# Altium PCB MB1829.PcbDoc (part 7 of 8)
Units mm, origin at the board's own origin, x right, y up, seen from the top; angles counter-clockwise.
Board outline 90 x 110 mm, 6 copper layers (Top Layer, Signal Layer 1, Signal Layer 2, Signal Layer 3, Signal Layer 4, Bottom Layer), stack 1.578 mm thick; 466 components, 354 nets, 2058 pads, 1522 vias.
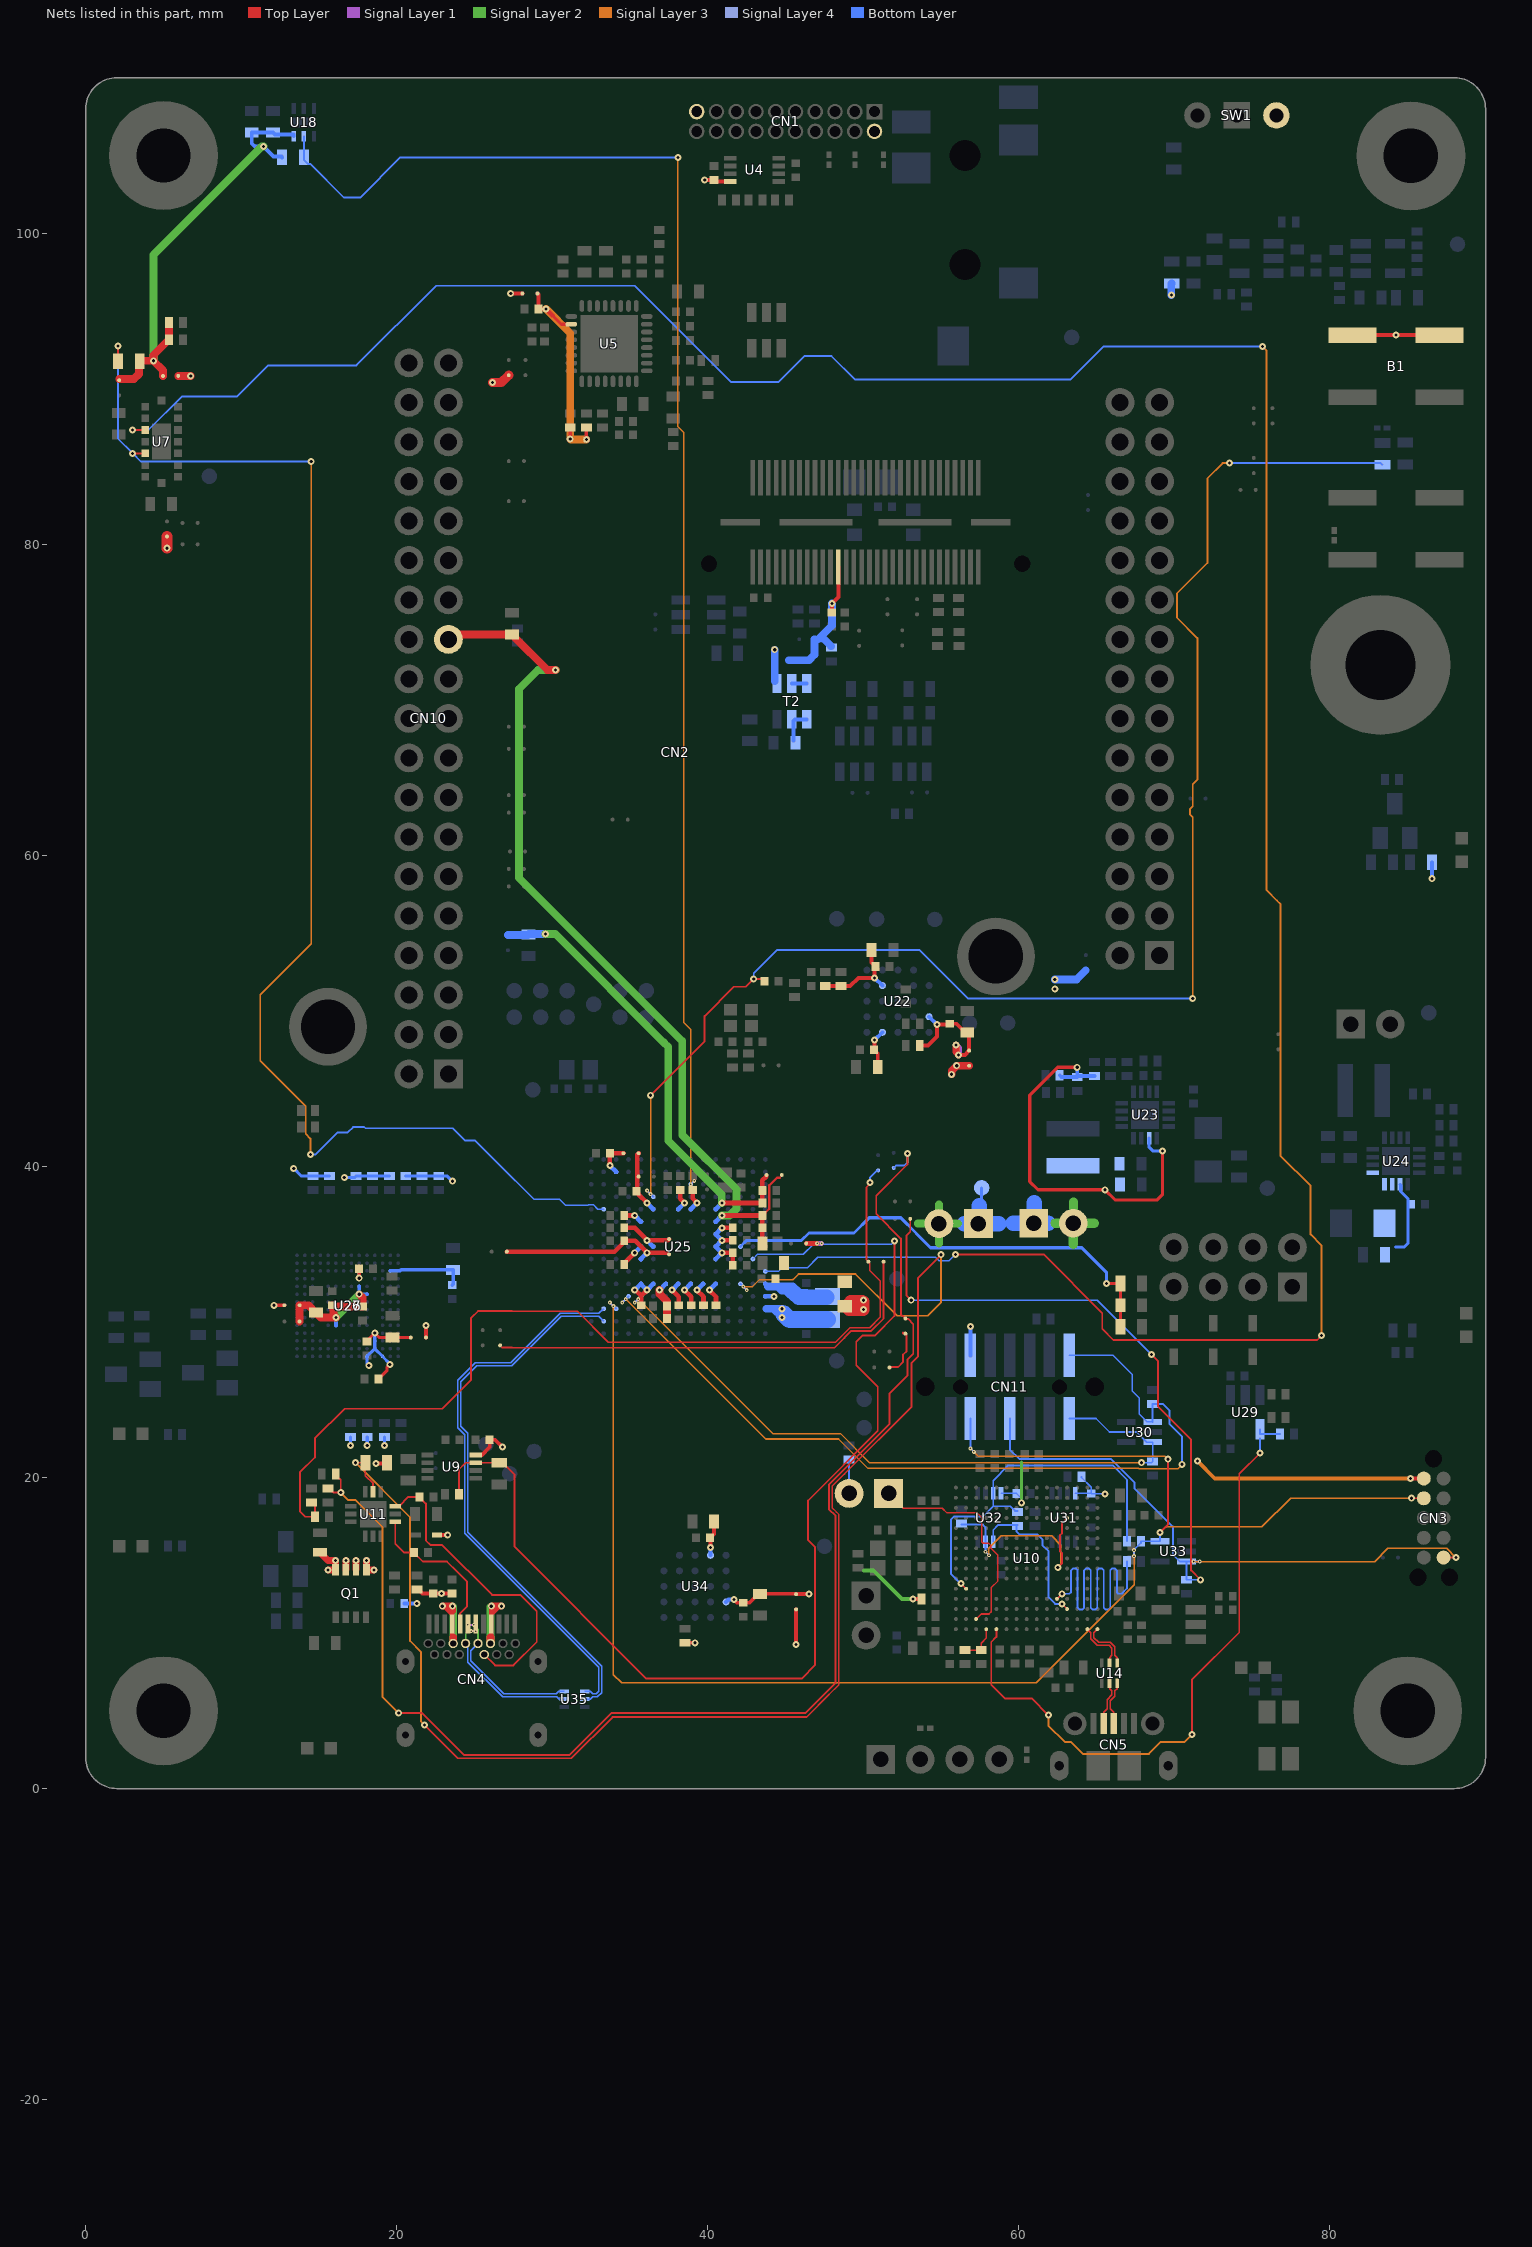
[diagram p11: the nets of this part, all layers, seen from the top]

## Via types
v1: diameter 0.45, hole 0.2, Top Layer to Bottom Layer, tented both sides, 1062 vias
v2: diameter 0.25, hole 0.1, Signal Layer 4 to Bottom Layer, tented both sides, 274 vias
v3: diameter 0.25, hole 0.1, Signal Layer 3 to Signal Layer 4, tented both sides, 119 vias
v4: diameter 0.25, hole 0.1, Top Layer to Signal Layer 1, tented both sides, 47 vias
v5: diameter 0.25, hole 0.1, Signal Layer 1 to Signal Layer 2, tented both sides, 20 vias

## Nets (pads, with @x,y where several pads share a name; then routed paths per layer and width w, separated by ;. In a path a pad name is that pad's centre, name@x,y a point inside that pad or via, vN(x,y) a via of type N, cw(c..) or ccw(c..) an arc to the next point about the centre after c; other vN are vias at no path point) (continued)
T.SWDIO: CN3.2 CN11.4 R124.1 U25.C13 U33.5 | length 103.7
  Top Layer w0.12: v1(69.075,16.475) 69.575,16.975 v1(69.575,21.175) ; v1(85.235,18.67) CN3.2@86.025,18.67
  Signal Layer 3 w0.09: v3(33.925,31.025) 33.925,7.325 34.45,6.8 61.1,6.8 61.55,7.25 67.4,13.1 v3(67.4,14.942) ; v3(57.11,21.65) 57.385,21.375 67.65,21.375 69.375,21.375 v1(69.575,21.175) ; v1(69.075,16.475) 69.425,16.825 75.625,16.825 77.47,18.67 v1(85.235,18.67)
  Signal Layer 4 w0.1: v2(33.7,31.25) v3(33.925,31.025) ; v2(56.885,21.875) v3(57.11,21.65) ; v3(67.4,14.942) v2(67.4,15.337)
  Bottom Layer w0.1: 33.8,31.15 U25.C13@34.1,30.85
  Bottom Layer w0.12: v2(33.7,31.25) U25.C13@34.1,30.85 ; v2(56.885,21.875) CN11.4@56.885,23.793 ; v2@67.4,15.35 67.85,15.8 R124.1@67.85,15.9 U33.5@69.075,15.9 v1(69.075,16.475)
T.SWO: CN3.6 CN11.8 R127.1 SB34.1 U33.3 | length 77.3
  Top Layer w0.12: SB34.1@53.013,36.625 53.013,35.788 52.765,35.54 52.765,31.71 v1(53.075,31.4) ; v1(68.535,27.9) 68.95,27.485 68.95,24.55 71.075,22.425 71.075,14.025 v1(71.675,13.425) ; CN3.6@87.305,14.85 v1(88.095,14.85)
  Signal Layer 3 w0.09: v3(71.231,14.6) 82.865,14.6 83.715,15.45 87.495,15.45 v1(88.095,14.85)
  Signal Layer 4 w0.1: v3(71.231,14.6) v2(71.626,14.6)
  Bottom Layer w0.12: v1(53.075,31.4) 65.035,31.4 v1(68.535,27.9) ; CN11.8@59.425,23.793 59.425,21.79 60.02,21.195 65.919,21.195 67.422,19.692 67.422,19.323 69.9,16.845 69.9,15.05 70.35,14.6 U33.3@70.775,14.6 ; v2(71.626,14.6) U33.3@70.775,14.6 ; v1(71.675,13.425) R127.1@70.775,13.425 U33.3@70.775,14.6
T.VCP_RX: CN11.13 R110.2 U25.D12 U30.1 | length 55.8
  Signal Layer 3 w0.1: v3(34.725,31.475) 43.725,22.475 48.4,22.475 50.271,20.604 67.69,20.604 67.72,20.575 70.244,20.575 70.475,20.806 v1(70.475,20.85)
  Signal Layer 4 w0.1: v2(34.5,31.25) v3(34.725,31.475)
  Bottom Layer w0.1: CN11.13@63.235,27.857 66.043,27.857 67.3,26.6 67.3,25.55 67.75,25.1 67.75,24.075 68.25,23.575 U30.1@68.6,23.575
  Bottom Layer w0.12: v2(34.5,31.25) U25.D12@34.9,31.65 ; U30.1@68.6,23.575 R110.2@68.6,24.725 69.275,24.725 69.675,24.325 69.675,23.45 70.475,22.65 v1(70.475,20.85)
T.VCP_TX: CN11.14 R118.1 U25.E12 U30.3 | length 45.6
  Signal Layer 3 w0.1: v3(35.525,31.475) 44.175,22.825 48.525,22.825 50.4,20.95 v1(67.875,20.95)
  Signal Layer 4 w0.1: v2(35.3,31.25) v3(35.525,31.475)
  Bottom Layer w0.1: CN11.14@63.235,23.793 64.957,23.793 65.825,22.925 67.575,22.925 68.225,22.275 U30.3@68.6,22.275 R118.1@68.6,21.025 68.525,20.95 v1(67.875,20.95)
  Bottom Layer w0.12: v2(35.3,31.25) U25.E12@35.7,31.65
T_NRST: JP5.1 U10.P3 | length 14.7
  Top Layer w0.1: 53.175,18.025 55.075,18.025 55.375,17.725 57.325,17.725 57.6,17.45 57.6,15.875 57.7,15.775 58.05,15.775 58.2,15.625 58.2,15.45 58.65,15 58.65,13.35 58.225,12.925 58.225,11.375 58.075,11.225 57.575,11.225 U10.P3@57.25,10.9
  Top Layer w0.12: JP5.1@51.62,18.975 52.57,18.025 53.175,18.025
T_NRSTa: JP5.2 R117.2 | length 2.2
  Bottom Layer w0.12: R117.2@49.075,21.15 49.08,21.145 JP5.2@49.08,18.975
T_PWR_EN: R115.2 U10.R5 U29.4 | length 41.8
  Top Layer w0.12: U10.R5@58.55,10.25 58.55,9.75 58.225,9.425 58.225,6.673 59.098,5.8 60.825,5.8 v1(61.9,4.725) ; v1(71.125,3.475) 71.125,6.995 74.165,10.035 74.165,20.24 v1(75.5,21.575)
  Signal Layer 3 w0.12: v1(61.9,4.725) 61.9,4.05 62.95,3 63.325,3 64.1,2.225 68.357,2.225 69.132,3 70.65,3 v1(71.125,3.475)
  Bottom Layer w0.12: v1(75.5,21.575) U29.4@75.5,22.515 ; U29.4@75.5,23.1 75.5,22.8 R115.2@76.8,22.8
T_PWR_EXT: R53.2 R54.2 U10.R4 | length 2.5
  Top Layer w0.1: R53.2@56.525,8.9 R54.2@57.575,8.9 57.575,9.35 57.9,9.675 U10.R4@57.9,10.25
T_SWCLKa: R126.2 U10.M11 | length 24.5
  Top Layer w0.12: U10.M11@62.45,12.2 v1(62.775,12.525)
  Bottom Layer w0.12: v1(62.775,12.525) 63.19,12.525 63.25,12.525 63.355,12.63 63.355,14.042 63.46,14.147 63.67,14.147 63.775,14.042 63.775,11.628 63.88,11.523 64.09,11.523 64.195,11.628 64.195,14.042 64.3,14.147 64.51,14.147 64.615,14.042 64.615,11.628 64.72,11.523 64.93,11.523 65.035,11.628 65.035,14.042 65.14,14.147 65.35,14.147 65.455,14.042 65.455,11.628 65.56,11.523 65.77,11.523 65.875,11.628 65.875,14.042 65.98,14.147 66.19,14.147 66.295,14.042 66.295,12.63 66.4,12.525 66.476,12.525 66.6,12.525 66.95,12.875 R126.2@66.95,14.6
T_SWDIO_IN: R123.2 U10.N12 U32.2 | length 10.1
  Top Layer w0.1: v1(62.775,11.875) U10.N12@63.1,11.55
  Bottom Layer w0.1: R123.2@59.85,16.9 R123.2@59.9,16.95 ; v1@62.745,11.875 v1(62.775,11.875)
  Bottom Layer w0.12: U32.2@58.35,15.875 58.35,16.625 58.675,16.95 59.85,16.95 R123.2@59.9,16.95 ; R123.2@59.85,16.9 59.85,16.525 60.025,16.35 61.187,16.35 61.515,16.022 61.515,15.644 61.912,15.247 61.912,12.294 62.331,11.875 62.738,11.875 v1@62.745,11.868
T_SWDIOa: R123.1 R124.2 U10.L2 U32.7 | length 24.6
  Top Layer w0.1: v1(56.275,13.175) U10.L2@56.6,12.85
  Bottom Layer w0.12: v1(56.275,13.175) 55.625,13.825 55.625,17.28 55.845,17.5 57.7,17.5 58.35,18.15 ; R123.1@59.9,17.85 59.75,17.85 59.45,18.15 58.35,18.15 ; R124.2@66.95,15.9 66.95,19.853 66.028,20.775 59.325,20.775 58.35,19.8 U32.7@58.35,18.975 58.35,18.15
T_SWOa: R121.2 U10.D12 U32.3 | length 14.2
  Top Layer w0.12: v1(62.5,14.225) 62.775,14.5 62.775,15.122 ; 62.771,15.122 62.64,15.253 62.64,16.291 62.775,16.426 62.775,17.075 U10.D12@63.1,17.4
  Signal Layer 3 w0.09: v3(58.075,15) 58.075,15.45 58.868,16.243 62.107,16.243 62.7,15.65 62.7,14.425 v1(62.5,14.225)
  Signal Layer 4 w0.1: v2(57.85,15.225) v3(58.075,15)
  Bottom Layer w0.12: R121.2@56.3,16.975 57.682,16.975 57.85,16.807 U32.3@57.85,15.875 v2(57.85,15.225)
TEMP_INTN: R56.1 U18.2 U25.J3 | length 94.6
  Signal Layer 3 w0.1: v1(38.07,104.875) 38.07,87.575 38.45,87.195 38.45,49.25 38.9,48.8 v3(38.9,38.85)
  Signal Layer 4 w0.1: v3(38.9,38.85) v2(39.125,39.075)
  Bottom Layer w0.1: v3(38.9,38.85) v2(39.125,39.075)
  Bottom Layer w0.12: U18.2@14.025,106.235 R56.1@14.026,104.875 R56.1@14.026,104.875 14.026,104.718 14.286,104.458 14.444,104.458 16.606,102.295 17.645,102.295 20.225,104.875 v1(38.07,104.875)
ToF_INTN: R9.1 U7.A3 U25.B5 | length 89.8
  Top Layer w0.12: R9.1@2.075,91.775 v1(2.075,92.75) ; v1(3.015,85.85) U7.A3@3.825,85.85
  Signal Layer 3 w0.12: v1(14.45,40.775) 14.45,41.795 14.148,42.097 14.148,43.863 11.22,46.791 11.22,51.034 14.5,54.314 v1(14.5,85.325)
  Bottom Layer w0.1: 27.425,39.281 27.856,38.85 ; 27.85,38.85 27.856,38.85 ; U25.B5@33.3,37.25 32.925,37.25 32.625,37.55 32.325,37.55 32.275,37.5 30.85,37.5 30.45,37.9 28.806,37.9 27.856,38.85
  Bottom Layer w0.12: v1(2.075,92.75) 2.075,86.79 v1(3.015,85.85) 3.54,85.325 v1(14.5,85.325) ; v1(14.45,40.775) 14.783,40.775 16.193,42.185 16.846,42.185 17.196,42.535 17.91,42.535 17.99,42.455 23.598,42.455 24.393,41.66 25.046,41.66 27.425,39.281
ToF_LPN: U7.A5 U25.R10 | length 186.6
  Top Layer w0.12: v1(3,87.35) U7.A5@3.825,87.35 ; v1(55.925,34.35) 61.585,34.35 65.36,30.575 65.36,29.56 66.078,28.842 79.167,28.842 v1(79.45,29.125)
  Signal Layer 3 w0.12: v1(75.65,92.725) 75.93,92.445 75.93,57.759 76.594,57.094 76.83,56.859 76.83,40.67 78.75,38.75 78.75,35.632 79.45,34.932 v1(79.45,29.125)
  Bottom Layer w0.1: U25.R10@43.7,33.25 44.55,33.25 44.775,33.475 46.392,33.475 47.072,34.155 54.64,34.155 54.845,33.95 55.525,33.95 v1(55.925,34.35)
  Bottom Layer w0.12: v1(3,87.35) 4.026,87.35 6.176,89.5 9.725,89.5 11.725,91.5 17.4,91.5 22.525,96.625 35.3,96.625 41.5,90.425 44.525,90.425 46.2,92.1 47.95,92.1 49.45,90.6 63.325,90.6 65.45,92.725 v1(75.65,92.725)
UCPD.ADC1: R39.2 R43.1 SB38.1 SB58.1 | length 61
  Top Layer w0.1: 27.425,30.7 31.6,30.7 33.6,28.7 48.203,28.7 49.138,29.635 50.41,29.635 51.075,30.3 51.075,32.645 50.42,33.3 50.42,33.739 50.322,33.837 SB38.1@50.322,33.875
  Top Layer w0.12: R39.2@14.525,18.4 14.555,18.4 14.75,18.205 R43.1@14.75,17.475 14.125,17.475 13.775,17.825 13.775,20.325 14.738,21.288 14.738,22.513 16.65,24.425 22.925,24.425 24.779,26.279 24.779,30.258 25.221,30.7 27.425,30.7 ; SB38.1@50.322,33.875 50.322,33.89 50.2,34.012 50.2,38.66 50.429,38.889 v1(50.429,38.979)
  Bottom Layer w0.12: v1(50.429,38.979) 50.433,38.983 50.433,39.308 50.815,39.69 50.854,39.69 50.914,39.75 SB58.1@50.95,39.75
UCPD.ADC2: R38.2 R40.1 SB40.1 SB57.2 | length 89.4
  Top Layer w0.12: R40.1@15.575,19.3 15.67,19.3 15.865,19.105 15.865,19.095 15.935,19.025 v1(16.4,19.025) 16.4,19.865 16.33,19.935 16.27,19.935 16.075,20.13 R38.2@16.075,20.225 ; v1(20.125,4.85) 21.636,4.85 24.316,2.17 31.12,2.17 33.8,4.85 46.25,4.85 48.215,6.815 48.215,17.533 47.785,17.963 47.785,19.546 51.675,23.436 51.675,25.4 52.825,26.55 52.825,27.57 53.21,27.955 53.21,29.865 52.872,30.203 52.722,30.203 52.415,30.51 52.415,35.36 50.825,36.95 50.825,38.125 52.825,40.125 v1(52.825,40.825)
  Signal Layer 3 w0.12: v1(16.4,19.025) 16.875,18.55 17.35,18.55 19.075,16.825 19.075,5.9 v1(20.125,4.85)
  Bottom Layer w0.12: SB57.2@51.95,39.902 52.108,40.06 52.638,40.06 52.825,40.247 v1(52.825,40.825)
UCPD.CC1: SB38.2 SB43.1 | length 28.9
  Top Layer w0.1: 27.425,28.35 48.15,28.35 48.775,28.975
  Top Layer w0.12: 26.775,28.35 27.425,28.35 ; 48.775,28.975 49.225,29.425 50.497,29.425 51.297,30.225 SB38.2@51.297,33.875
UCPD.CC2: SB40.2 SB46.1 | length 3
  Top Layer w0.12: SB46.1@51.675,27.075 51.7,27.1 52.225,27.1 52.558,27.433 52.558,27.908 52.775,28.125 52.775,29.148 52.7,29.223 SB40.2@52.7,29.25 ; 52.558,29.25 52.558,29.325
UCPD.DBn: R37.1 R41.1 U9.7 U25.P9 | length 74.3
  Top Layer w0.12: R41.1@24,18.925 24,20.525 24.425,20.95 U9.7@25.075,20.95 R37.1@26.525,20.95 ; R37.1@26.6,20.95 26.8,20.95 27.575,20.175 27.575,15.55 36.05,7.075 46.025,7.075 46.9,7.95 46.9,15.525 46.45,15.975 46.45,18.522 50.925,22.997 50.925,25.825 49.54,27.21 49.54,28.73 49.95,29.14 50.75,29.14 52,30.39 v1(52,35.2)
  Bottom Layer w0.1: U25.P9@42.9,34.05 43.2,34.35 46.136,34.35 46.786,35 51.045,35 51.8,35 v1(52,35.2)
UCPD.FLT: R36.1 U11.11 U25.N11 | length 100.1
  Top Layer w0.1: 47.792,6.05 48.425,6.683 48.425,17.625 48.275,17.775 48.27,17.775 48.005,18.04 48.005,19.455 48.775,20.225
  Top Layer w0.12: v1(17.35,20.95) R36.1@17.975,20.95 17.975,20.125 18.475,19.625 U11.11@18.475,19.075 ; v1(21.775,4.1) 23.925,1.95 31.225,1.95 33.875,4.6 46.342,4.6 47.792,6.05 ; 48.775,20.225 53.1,24.55 53.1,27.375 53.5,27.775 53.5,32.825 v1(55,34.325)
  Signal Layer 3 w0.1: v3(42.275,32.275) 42.875,32.275 43.325,32.725 45.475,32.725
  Signal Layer 3 w0.12: v1(17.35,20.95) 20.85,17.45 20.85,9.5 21.55,8.8 21.55,4.325 v1(21.775,4.1) ; 45.475,32.725 45.835,33.085 49.49,33.085 52.175,30.4 54.125,30.4 55,31.275 v1(55,34.325)
  Signal Layer 4 w0.1: v3(42.275,32.275) v2(42.5,32.05)
  Bottom Layer w0.12: U25.N11@42.1,32.45 v2(42.5,32.05)
UCPD_CC1_C: C90.2 CN4.A5 U11.7 | length 9.9
  Top Layer w0.12: U11.7@19.9,17.15 19.9,15.75 20.475,15.175 C90.2@21.1,15.175 21.675,14.6 23.222,14.6 23.892,13.93 23.896,13.93 23.99,13.836 23.99,13.832 24.525,13.297 24.525,11.726 24.074,11.275 CN4.A5@24.074,10.58
UCPD_CC2_C: C79.2 CN4.B5 U11.9 | length 20
  Top Layer w0.12: U11.9@19.9,18.15 20.15,18.15 20.75,18.75 C79.2@21.45,18.75 21.875,18.325 21.875,15.95 22.17,15.655 22.92,15.655 26.125,12.45 27.95,12.45 29,11.4 29,9.425 27.5,7.925 26.319,7.925 CN4.B5@25.624,8.62
USB_DEV_HS_CN_N: CN5.2 U14.5 | length 2.9
  Top Layer w0.095: CN5.2@65.45,4.175 65.45,4.898 65.678,5.125 65.678,5.728 65.978,6.028 65.978,6.275 65.825,6.428 U14.5@65.825,6.775
USB_DEV_HS_CN_P: CN5.3 U14.6 | length 2.9
  Top Layer w0.095: CN5.3@66.1,4.175 66.1,4.898 65.873,5.125 65.873,5.647 66.173,5.947 66.173,6.275 66.325,6.428 U14.6@66.325,6.775
USB_DEV_HS_N: U10.R14 U14.2 | length 3.3
  Top Layer w0.095: U10.R14@64.4,10.25 64.627,10.023 64.627,9.622 65.044,9.205 65.795,9.205 65.978,9.023 65.978,8.575 65.825,8.423 U14.2@65.825,8.075
USB_DEV_HS_P: U10.R15 U14.1 | length 3.3
  Top Layer w0.095: U10.R15@65.05,10.25 64.822,10.023 64.822,9.703 65.125,9.4 65.876,9.4 66.173,9.103 66.173,8.575 66.325,8.423 U14.1@66.325,8.075
USBC.HS_N: U25.B14 U35.2 | length 36.1
  Bottom Layer w0.095: U35.2@32.075,5.75 32.45,5.75 32.6,5.9 32.9,5.9 33.175,6.175 33.175,7.87 24.557,16.488 24.557,22.818 24.557,22.844 24.12,23.281 24.12,26.17 25.13,27.18 27.406,27.18 30.578,30.353 32.997,30.353 U25.B14@33.3,30.05
USBC.HS_P: U25.B13 U35.1 | length 36.1
  Bottom Layer w0.095: U35.1@32.075,6.25 32.45,6.25 32.605,6.095 32.819,6.095 32.98,6.256 32.98,7.789 24.362,16.407 24.362,16.488 24.362,22.763 23.925,23.2 23.925,26.251 25.049,27.375 27.325,27.375 30.498,30.548 32.997,30.548 U25.B13@33.3,30.85
USBC_CN_HS_N: CN4.A7 CN4.B7 U35.5 | length 9.8
  Signal Layer 1 w0.12: v5@24.795,10.125 v4(25.075,10.125)
  Signal Layer 2 w0.104: CN4.B7@24.424,9.33 24.424,9.999 24.55,10.125 v5(24.775,10.125)
  Bottom Layer w0.095: CN4.B7@24.424,9.33 24.424,9.193 24.575,9.043 24.575,8.135 26.807,5.903 30.278,5.903 30.43,5.75 U35.5@30.775,5.75
USBC_CN_HS_P: CN4.A6 CN4.B6 U35.6 | length 9.9
  Signal Layer 1 w0.12: v4(24.575,10.525) v5(24.95,10.525)
  Signal Layer 2 w0.104: v5(24.95,10.525) 25.224,10.251 CN4.B6@25.224,9.33
  Bottom Layer w0.095: CN4.B6@25.224,9.33 24.77,8.876 24.77,8.216 26.888,6.098 30.264,6.098 30.417,6.25 U35.6@30.775,6.25
USER_Button: C29.2 R68.1 U25.F4 | length 96
  Top Layer w0.1: v1(36.325,44.575) 37.675,45.925
  Top Layer w0.12: 37.675,45.925 39.787,48.037 39.787,49.662 41.675,51.55 42.44,51.55 v1(42.95,52.06) 43.49,52.06 C29.2@43.65,51.9
  Signal Layer 3 w0.1: v3(36.325,38.225) v1(36.325,44.575)
  Signal Layer 3 w0.12: v1(71.175,50.8) 71.175,62.456 70.99,62.641 70.99,62.959 71.175,63.144 71.175,64.575 71.475,64.875 71.475,73.972 70.165,75.282 70.165,76.84 72.125,78.8 72.125,84.25 73.1,85.225 v1(73.55,85.225)
  Signal Layer 4 w0.1: v2(36.1,38.45) v3(36.325,38.225)
  Bottom Layer w0.12: v2(36.1,38.45) U25.F4@36.5,38.05 ; v1(42.95,52.06) 42.95,52.419 44.456,53.925 53.6,53.925 56.725,50.8 v1(71.175,50.8) ; v1(73.55,85.225) 83.265,85.225 R68.1@83.375,85.115
V11: C39.2 C44.2 C60.2 C140.2 L8.1 U25.E6 U25.E11 U25.F11 U25.H5 U25.R13 | length 10.8
  Top Layer w0.3: C44.2@34.625,36.85 v1(35.3,36.85) ; v1(35.3,32.05) 35.35,32.05 35.725,31.675 ; C60.2@35.725,31.075 35.725,31.675 ; v1@36.1,32.05 35.725,31.675 ; C39.2@38.225,38.475 38.225,37.925 v1@38.5,37.65
  Bottom Layer w0.3: v1(35.3,32.05) U25.E11@35.693,32.443 ; v1(35.3,36.85) U25.E6@35.7,36.45 ; U25.E11@35.7,32.45 U25.E11@35.693,32.443 ; U25.F11@36.5,32.45 v1(36.1,32.05) 36.087,32.05 U25.E11@35.693,32.443 ; U25.H5@38.1,37.25 v1(38.5,37.65) ; U25.R13@43.7,30.85 U25.R13@43.775,30.85
  Bottom Layer w0.5: U25.R13@43.775,30.85 44.225,30.85 ; v1(44.775,30.3) 44.225,30.85 ; v1@44.8,30.85 44.225,30.85
  Bottom Layer w0.8: 44.97,30.525 44.97,30.529
  Bottom Layer w1.1: 44.9,30.499 45.198,30.2 ; 45.298,30.15 C140.2@46.325,30.15 ; C140.2@46.34,30.15 L8.1@47.7,30.15
  other v1: 44.775,30.85
VBAT: C36.2 SB29.2 U25.C2 | length 2.2
  Top Layer w0.3: v1(33.7,40.05) C36.2@33.7,40.85 ; C36.2@33.7,40.85 SB29.2@34.575,40.85
  Bottom Layer w0.3: v1(33.7,40.05) U25.C2@34.1,39.65
VBUS_SENSE: C59.2 R31.1 R32.2 U25.N8 | length 30.1
  Top Layer w0.2: v1(65.625,32.475) R31.1@66.525,32.475 C59.2@66.525,31.075 R32.2@66.525,29.7
  Bottom Layer w0.2: U25.N8@42.1,34.85 42.5,35.25 46.025,35.25 46.5,35.725 49.4,35.725 50.375,36.7 52.4,36.7 53.38,35.72 53.38,35.714 54.319,34.775 64.05,34.775 65.625,33.2 v1(65.625,32.475)
VBUSc: C93.2 C94.2 C147.2 CN4.A4 CN4.A9 CN4.B4 CN4.B9 D4.1 Q1.5 Q1.6 Q1.7 Q1.8 R48.2 U12.1 | length 21.9
  Top Layer w0.25: R48.2@21.3,12.8 21.395,12.8 21.645,12.55 C93.2@22.35,12.55 v1(22.875,12.55) 23.541,12.55 C94.2@23.55,12.541 ; D4.1@22.575,16.3 v1(23.275,16.3)
  Top Layer w0.3: v1@23.049,11.724 23.574,11.199 ; 23.574,11.425 CN4.A4@23.574,10.58 23.574,9.38 CN4.B9@23.624,9.33 ; CN4.B4@26.024,9.33 26.074,9.38 CN4.A9@26.074,10.58 v1(26.074,11.724) ; 26.074,11.199 v1@26.599,11.724
  Top Layer w0.45: U12.1@15.05,15.2 15.575,14.675 v1(16.05,14.675) Q1.8@16.05,14.075 16.025,14.05 v1(15.575,14.05) ; Q1.7@16.725,14.075 v1(16.725,14.675) ; Q1.6@17.375,14.075 v1(17.375,14.675) ; v1(18.05,14.675) Q1.5@18.05,14.075 18.075,14.05 v1(18.525,14.05) ; v1@23.049,11.724 v1(22.924,11.724) v1(23.574,11.724) 23.574,11.425 ; v1(26.074,11.724) v1(26.724,11.724) v1@26.599,11.724
  Top Layer w0.5: CN4.B9@23.624,9.33 23.625,9.725 ; CN4.B4@26.024,9.33 26.025,9.725
  Signal Layer 2 w0.5: v1(23.574,11.724) 23.624,11.674 CN4.B9@23.624,9.33 ; CN4.B4@26.024,9.33 26.024,11.674 v1(26.074,11.724)
  Bottom Layer w0.25: C147.2@20.478,11.9 v1(21.286,11.9)
VCC_eMMC: C57.2 C58.2 C66.2 SB39.2 SB41.2 U26.E6 U26.F5 U26.J10 U26.K9 U27.E6 U27.F5 U27.J10 U27.K9 | length 11.5
  Top Layer w0.5: SB41.2@13.75,30.025 SB39.2@13.75,31.075 14.325,31.075 C57.2@14.8,30.6 15.114,30.286 v1(16.085,30.286) 15.925,30.446 C58.2@15.925,31 ; C58.2@15.85,31.075 C58.2@15.925,31 ; v1(17.585,31.786) 17.8,31.571 C66.2@17.8,31 C58.2@15.925,31
  Signal Layer 2 w0.5: v1(16.085,30.286) v1(17.585,31.786)
  Bottom Layer w0.25: U27.J10@15.585,30.286 v1(16.085,30.286) U27.K9@16.085,29.786 ; U27.E6@17.585,32.286 v1(17.585,31.786) U27.F5@18.085,31.786
VCCQ_eMMC: C55.2 C67.2 C69.2 C70.2 R95.2 R96.2 R97.2 R98.2 R99.2 R100.2 R101.2 R102.2 R112.2 R113.2 R114.2 SB44.2 U26.C6 U26.M4 U26.N4 U26.P3 U26.P5 U27.C6 U27.M4 U27.N4 U27.P3 U27.P5 | length 19.5
  Top Layer w0.2: C69.2@18.085,28.736 18.085,28.79 v1(18.585,29.29) 18.875,29 C67.2@19.725,29 SB44.2@20.9,29 ; C70.2@18.833,26.338 19.359,26.865 19.359,27.084 v1(19.55,27.275)
  Top Layer w0.25: C55.2@17.575,33.425 17.585,33.415 v1(17.585,32.815)
  Bottom Layer w0.2: v1(13.375,39.875) 13.875,39.375 R102.2@14.625,39.375 R101.2@15.675,39.375 ; v1(16.625,39.3) 17.3,39.3 R100.2@17.375,39.375 R99.2@18.45,39.375 R98.2@19.525,39.375 ; v1(17.025,22.05) R114.2@17.025,22.6 ; v1(17.585,32.815) U27.C6@17.585,33.286 ; v1(18.1,22.05) R113.2@18.1,22.6 ; v1(18.2,27.2) 18.085,27.315 U27.P5@18.085,27.786 U27.N4@18.585,28.286 ; v1(18.585,29.29) U27.M4@18.585,28.786 U27.N4@18.585,28.286 ; v1(19.2,22.05) R112.2@19.2,22.6 ; v1(19.55,27.275) 19.55,27.313 19.085,27.778 U27.P3@19.085,27.786 U27.N4@18.585,28.286 ; R97.2@20.575,39.375 R96.2@21.625,39.375 R95.2@22.7,39.375 23.25,39.375 v1(23.575,39.05)
VDD: B1.3 B1.4 C2.1 C72.1 C143.1 C144.1 CN1.2 CN1.19 CN3.1 CN11.3 JP2.2 R36.2 R50.2 R62.1 R79.1 R119.1 SB1.1 SB3.1 SB4.1 SB12.1 SB27.1 SB39.1 SB44.1 SB47.1 SB51.1 SB56.1 SW1.2 T2.4 U4.8 U9.8 U31.8 U32.8 | length 59.6
  Top Layer w0.25: v1(12.1,31.075) SB39.1@12.775,31.075 ; v1(18.675,20.9) 19.325,20.9 R36.2@19.375,20.95 ; SB44.1@21.875,29 v1(21.875,29.775) ; U9.8@25.075,21.45 25.475,21.45 25.975,21.95 C72.1@25.975,22.425 26.325,22.425 v1(26.8,21.95) ; v1(27.325,96.125) SB1.1@28.075,96.125 ; v1(39.8,103.425) C2.1@40.4,103.425 40.5,103.325 U4.8@41.45,103.325 ; v1(45.675,9.275) SB47.1@45.675,11.525 ; v1(53.2,12.2) R50.2@53.75,12.2 ; B1.4@81.45,93.45 B1.3@87.05,93.45 ; v1(85.175,19.935) CN3.1@86.03,19.935
  Top Layer w0.5: SB4.1@5.95,90.825 v1(6.75,90.825) ; v1(55.675,45.925) 55.675,46.15 v1(56,46.475) SB27.1@56.8,46.475
  Top Layer w0.6: v1(26.15,90.4) 26.725,90.4 SB3.1@27.2,90.875
  Top Layer w0.7: v1(5.225,79.75) SB12.1@5.225,80.5
  Signal Layer 2 w0.2: v1(60.175,18.375) 60.175,21
  Signal Layer 2 w0.25: 50.05,14.025 50.65,14.025 52.475,12.2 v1(53.2,12.2)
  Signal Layer 2 w0.6: 62.325,36.35 JP2.2@63.495,36.35 ; 63.495,35.002 JP2.2@63.495,36.35 ; JP2.2@63.503,36.342 64.851,36.342 ; 63.511,37.715 63.511,36.366 JP2.2@63.495,36.35
  Signal Layer 3 w0.25: v1(71.475,21.05) 72.59,19.935 v1(85.175,19.935)
  Bottom Layer w0.1: U32.8@58.85,18.975 C143.1@59.85,18.975 60.175,18.65 v1(60.175,18.375) ; U31.8@63.625,18.975 C144.1@64.65,18.975 ; R119.1@64.025,20.05 64.025,20 64.65,19.375 C144.1@64.65,18.975 ; v1(65.525,18.95) 64.675,18.95 C144.1@64.65,18.975
  Bottom Layer w0.25: CN11.3@56.885,27.857 v1(56.885,29.715) ; v1(86.55,58.5) R79.1@86.55,59.55
  Bottom Layer w0.5: T2.4@44.3,71.196 SB51.1@44.3,72.546 v1(44.3,73.221) ; v1(62.306,52.026) 63.714,52.026 SB56.1@64.3,52.613 ; v1(69.8,96.025) 69.8,96.75 R62.1@69.825,96.775
  other v1: 62.306,51.404 84.25,93.45
VDD_HEXASPI: C84.2 C88.2 C97.2 C99.2 R52.2 SB47.2 U34.D1 U34.E4 | length 8.7
  Top Layer w0.25: R52.2@38.525,9.375 v1(39.175,9.375) ; v1(40.175,15.5) 40.175,16.1 C88.2@40.15,16.125 40.4,16.375 C84.2@40.4,17.175 ; v1(41.675,12.15) 41.875,11.95 C99.2@42.275,11.95 42.675,11.95 43.25,12.525 C97.2@43.35,12.525 45.65,12.525 SB47.2@45.675,12.5 v1(46.5,12.5)
  Bottom Layer w0.25: U34.D1@40.175,15 v1(40.175,15.5) ; U34.E4@41.175,12 41.325,12.15 v1(41.675,12.15)
VDD_LCD: C23.2 C124.2 CN2.38 R72.2 SB50.2 SB51.2 T2.1 T2.2 T2.5 T2.6 | length 12.2
  Top Layer w0.25: C23.2@47.975,75.621 v1(47.975,76.196) 48.389,76.61 CN2.38@48.389,78.54
  Bottom Layer w0.25: T2.5@45.4,71.046 T2.6@46.35,71.046 ; C124.2@45.5,67.371 T2.2@45.5,68.646 ; T2.2@45.6,68.746 T2.1@46.35,68.746
  Bottom Layer w0.5: SB51.2@45.2,72.546 SB51.2@45.275,72.546 46.5,72.546 46.85,72.896 SB50.2@46.85,73.896 ; 47.1,73.896 47.975,74.771 v1(47.975,76.196) ; 47.475,73.896 R72.2@47.925,73.446
VDD_MCU: C40.2 C42.2 C46.2 C47.2 C49.2 C51.2 C53.2 C54.2 C61.2 C62.2 C63.2 C64.2 C65.2 C68.2 JP3.2 L3.1 SB29.1 SB32.1 SB35.1 SB36.1 U25.E8 U25.F5 U25.F8 U25.G11 U25.H11 U25.J5 U25.J11 U25.K11 U25.L7 U25.L8 U25.L9 U25.L11 | length 35.2
  Top Layer w0.3: C46.2@34.625,36.05 35.313,36.05 36.1,35.263 36.1,35.25 37.431,35.25 SB35.1@37.506,35.325 ; C53.2@34.625,33.7 34.73,33.805 34.73,33.88 v1(35.3,34.45) ; C42.2@35.425,38.4 35.53,38.295 35.53,38.22 v1(36.1,37.65) ; C42.2@35.465,38.385 35.465,39.35 35.465,40.765 SB29.1@35.55,40.85 ; v1@37.7,32.05 38.125,31.625 C61.2@38.125,31.075 ; v1@38.5,32.05 38.925,31.625 C62.2@38.925,31.075 ; C40.2@39.025,38.475 39.025,37.938 39.3,37.663 v1(39.3,37.65) ; v1(39.3,32.05) 39.725,31.625 C63.2@39.725,31.075 ; v1(40.1,32.05) 40.525,31.625 C64.2@40.525,31.075 ; v1(40.9,34.45) C51.2@41.6,34.45 C54.2@41.6,33.65 ; v1(40.9,35.25) C49.2@41.6,35.25 ; v1(40.9,36.05) C47.2@41.6,36.05 ; SB36.1@46.325,35.05 v4(47.025,35.05)
  Top Layer w0.5: v1@36.9,32.05 36.9,31.8 37.375,31.325 37.375,31.025 C68.2@37.375,30.225
  Top Layer w0.8: L3.1@48.8,31 L3.1@48.875,31 ; v1@49.92,31.32 49.195,31.32 L3.1@48.875,31 ; v1@49.998,31.318 49.998,30.816 49.981,30.8 49.075,30.8 L3.1@48.875,31
  Signal Layer 1 w0.3: v4(47.025,35.05) v5(47.325,35.05)
  Signal Layer 2 w0.5: 53.5,36.325 JP3.2@54.855,36.325 ; 54.855,35.045 JP3.2@54.855,36.325 ; 54.855,37.55 JP3.2@54.855,36.325 ; 56.075,36.325 JP3.2@54.855,36.325
  Bottom Layer w0.3: v1(35.3,34.45) U25.E8@35.7,34.85 ; v1(36.1,35.25) U25.F8@36.5,34.85 ; v1(36.1,37.65) U25.F5@36.5,37.25 ; v1(36.9,32.05) U25.G11@37.3,32.45 ; v1(37.7,32.05) U25.H11@38.1,32.45 ; v1(38.5,32.05) U25.J11@38.9,32.45 ; U25.J5@38.9,37.25 v1(39.3,37.65) ; v1(39.3,32.05) U25.K11@39.7,32.45 ; v1(40.1,32.05) U25.L11@40.5,32.45 ; U25.L9@40.5,34.05 v1(40.9,34.45) U25.L8@40.5,34.85 v1(40.9,35.25) U25.L7@40.5,35.65 v1(40.9,36.05)
  other v1: 50,30.8 50,31.4
VDD_MEMS: C113.1 C114.2 R7.2 R8.2 R9.2 R56.2 SB4.2 SB5.1 U18.3 | length 29.9
  Top Layer w0.5: SB5.1@2.15,90.625 3.1,90.625 3.422,90.947 3.422,91.722 R9.2@3.475,91.775 3.5,91.8 v1(4.35,91.8) ; SB4.2@4.975,90.825 4.975,91.175 v1(4.35,91.8) ; R7.2@5.35,94.25 R8.2@5.35,93.15 5.35,93.055 5.345,93.05 5.25,93.05 4.35,92.15 v1(4.35,91.8)
  Signal Layer 2 w0.5: v1(4.35,91.8) 4.35,98.598 11.327,105.575 v1(11.425,105.575)
  Bottom Layer w0.25: R56.2@12.626,104.875 12.579,104.922 12.078,104.922 v1(11.425,105.575) 10.875,105.575 10.675,105.775 C114.2@10.675,106.469 C113.1@12.05,106.469 12.163,106.356 13.365,106.356 13.375,106.346 U18.3@13.375,106.235
VDD_OCTOSPI: C26.2 C27.2 C30.2 C31.2 C34.2 C35.2 R20.2 R21.2 R25.2 SB27.2 U22.B4 U22.D1 U22.E4 | length 17
  Top Layer w0.25: R20.2@47.55,51.6 R21.2@48.55,51.6 49.15,51.6 49.675,52.125 v1(50.725,52.125) 50.725,52.8 C27.2@50.775,52.85 50.525,53.1 C26.2@50.525,53.925 ; v1(50.725,48.125) 50.725,47.55 C34.2@50.675,47.5 50.925,47.25 C35.2@50.925,46.4 ; R25.2@53.625,47.775 54.15,47.775 54.725,48.35 v1(54.725,49.125) 55.5,49.125 C30.2@55.55,49.175 55.975,49.175 56.55,48.6 C31.2@56.675,48.6 56.8,48.475 SB27.2@56.8,47.45 56.525,47.175 v1(56.125,47.175)
  Top Layer w0.45: v1(55.95,47.8) 55.95,47.35 v1(56.125,47.175)
  Signal Layer 1 w0.45: v1(55.95,47.8) 56.125,47.625 v1(56.125,47.175)
  Bottom Layer w0.25: v1(50.725,48.125) U22.E4@51.225,48.625 ; v1(50.725,52.125) U22.B4@51.225,51.625 ; U22.D1@54.225,49.625 v1(54.725,49.125)
VDD_SMPS: C52.2 C56.2 L3.2 U25.R12 | length 0.6
  Bottom Layer w0.3: U25.R12@43.7,31.65 v1(44.25,31.65)
VDD_USB: C50.2 SB35.2 SB37.2 U25.E9 | length 11.5
  Top Layer w0.3: SB37.2@27.075,34.525 27.425,34.525 34,34.525 34.52,35.045 34.52,35.12 C50.2@34.625,35.225 35.325,35.225 v1(36.1,34.45) 37.375,34.45 37.381,34.456
  Bottom Layer w0.3: U25.E9@35.7,34.05 v1(36.1,34.45)
VDDA: C25.2 C45.2 C48.2 CN10.23 L2.2 SB31.2 U25.L6 | length 59.2
  Top Layer w0.15: C45.2@43.525,36.85 43.95,37.275 43.95,38.783 44.443,39.275 44.45,39.275 44.625,39.275
  Top Layer w0.2: C45.2@43.5,36.85 C45.2@43.525,36.85
  Top Layer w0.3: v1(40.9,36.85) C45.2@43.5,36.85 43.5,35.075 L2.2@43.525,35.05
  Top Layer w0.5: CN10.23@23.32,73.884 23.636,74.2 25.425,74.2 C25.2@27.4,74.2 27.525,74.2 27.595,74.13 27.595,74.005 29.675,71.925 v1(30.2,71.925)
  Signal Layer 2 w0.5: v1(30.2,71.925) 29.086,71.925 27.85,70.689 27.85,58.559 38.35,48.059 38.35,42.023 41.85,38.523 41.85,37.3 41.4,36.85 v1(40.9,36.85)
  Bottom Layer w0.3: U25.L6@40.5,36.45 v1(40.9,36.85)
VDDI: C137.2 C139.2 U26.C2 U27.C2 | length 5.1
  Bottom Layer w0.23: U27.C2@19.585,33.286 20.211,33.286 20.275,33.35 20.897,33.35 C137.2@23.625,33.35 23.625,32.425 C139.2@23.575,32.375
VDDMCU_SMPS: C133.2 C134.2 JP2.1 JP3.1 L7.2 R84.1 R85.2 R86.2 TP22.1 U23.14 | length 33.6
  Top Layer w0.2: v1(63.75,46.375) 62.5,46.375 60.7,44.575 60.7,39.025 61.225,38.5 v1(65.525,38.5) 66.175,37.85 68.9,37.85 69.225,38.175 v1(69.225,41)
  Bottom Layer w0.2: 57.6,37.695 TP22.1@57.6,38.625 ; U23.14@68.372,41.814 68.372,41.235 68.607,41 v1(69.225,41)
  Bottom Layer w0.25: R85.2@62.622,45.866 62.747,45.741 R86.2@63.747,45.741 63.75,45.744 v1(63.75,46.375) ; R86.2@63.822,45.816 R84.1@64.847,45.816
  Bottom Layer w0.8: JP3.1@57.395,36.325 JP3.1@57.45,36.38 ; JP2.1@60.955,36.35 JP2.1@60.974,36.369
  Bottom Layer w1: JP3.1@56.5,36.325 JP3.1@57.395,36.325 58.705,36.325 ; JP3.1@57.45,36.38 57.45,37.475 ; 59.645,36.35 JP2.1@60.955,36.35 61.9,36.35 ; JP2.1@60.974,36.369 60.974,37.65
VIN: C135.2 C136.2 R103.2 U24.10 U24.11 U24.12 U24.13 | length 4.9
  Bottom Layer w0.2: 84.2,34.825 84.775,34.825 85.025,35.075 85.025,37.175 85.025,37.91 84.55,38.385 84.55,38.8 U24.10@84.5,38.85
VL_AUDIO: C8.1 R13.2 R14.2 SB1.2 U5.26 | length 15.1
  Top Layer w0.25: SB1.2@29.05,96.125 29.1,96.075 C8.1@29.1,95.125 v1(29.6,95.125) 30.575,94.15 U5.26@31.225,94.15 ; v1(31.15,86.775) R13.2@31.15,87.5 ; v1(32.187,86.74) 32.182,86.735 32.182,87.475 R14.2@32.207,87.5
  Signal Layer 3 w0.5: v1(29.6,95.125) 31.15,93.575 v1(31.15,86.775) 31.185,86.74 v1(32.187,86.74)
VLX_SMPS: C138.2 L8.2 U25.R11 | length 5.4
  Bottom Layer w0.3: U25.R11@43.7,32.45 43.875,32.275
  Bottom Layer w0.5: 43.875,32.275 44.5,32.275 ; 45.461,32.275 44.75,32.275 44.5,32.275 ; 45.526,32.025 45.466,32.025 45.461,32.025 44.75,32.025 44.5,32.275
  Bottom Layer w1: 45.354,32.025 45.838,31.605 46.32,31.605 C138.2@46.325,31.6 L8.2@47.65,31.6
VREFP: C41.2 C43.2 C125.2 SB31.1 SB55.2 U25.L5 | length 29.8
  Top Layer w0.3: v1(40.9,37.65) C43.2@43.5,37.65 43.5,39.1 SB31.1@43.75,39.35
  Signal Layer 2 w0.5: v1(29.55,54.95) 30.186,54.95 37.175,47.961 37.45,47.686 37.45,41.65 40.9,38.2 v1(40.9,37.65)
  Bottom Layer w0.3: U25.L5@40.5,37.25 v1(40.9,37.65)
  Bottom Layer w0.5: SB55.2@27.15,54.875 28.425,54.875 C125.2@28.475,54.925 28.5,54.95 v1(29.55,54.95)
pads on no net: CN1.3 CN1.7 CN1.8 CN1.9 CN1.10 CN1.11 CN1.13 CN1.14 CN1.15 CN1.16 CN1.17 CN1.18 CN2.2 CN2.20 CN2.25 CN2.30 CN2.31 CN2.32 CN2.33 CN2.34 CN2.35 CN2.37 CN2.39 CN2.41 CN2.42 CN2.45 CN2.46 CN2.47 CN2.48 CN2.50 CN2.51 CN2.52 CN2.54 CN2.55 CN2.56 CN2.58 CN2.59 CN2.65 CN2.66 CN3.7 CN3.9 CN3.11 CN3.12 CN3.13 CN4.A2 CN4.A3 CN4.A8 CN4.A10 CN4.A11 CN4.B2 CN4.B3 CN4.B8 CN4.B10 CN4.B11 CN5.4 CN6.5 CN6.7 CN6.MT1 CN6.MT2 CN9.17 CN9.18 CN10.21 CN10.22 CN11.0 CN11.1 CN11.2 CN11.9 SB59.1 U4.3 U5.19 U5.20 U5.23 U5.24 U7.C5 U9.3 U10.A1 U10.A2 U10.A3 U10.A4 U10.A5 U10.A6 U10.A8 U10.A9 U10.A10 U10.A11 U10.A12 U10.A13 U10.B1 U10.B2 U10.B3 U10.B4 U10.B5 U10.B6 U10.B7 U10.B8 U10.B9 U10.B10 U10.B11 U10.B12 U10.B13 U10.B14 U10.B15 U10.C2 U10.C3 U10.C4 U10.C11 U10.C12 U10.C13 U10.C14 U10.C15 U10.D1 U10.D2 U10.D3 U10.D4 U10.D10 U10.D11 U10.D13 U10.D14 U10.E1 U10.E2 U10.E3 U10.E4 U10.E12 U10.E13 U10.E14 U10.E15 U10.F1 U10.F4 U10.F14 U10.G4 U10.G14 U10.G15 U10.H1 U10.H2 U10.H3 U10.H4 U10.H14 U10.H15 U10.J2 U10.J3 U10.J4 U10.K1 U10.K2 U10.K3 U10.K12 U10.K14 U10.K15 U10.L1 U10.L3 U10.L12 U10.L13 U10.L14 U10.L15 U10.M2 U10.M3 U10.M4 U10.M5 U10.M6 U10.M7 U10.M12 U10.M13 U10.M14 U10.M15 U10.N2 U10.N4 U10.N5 U10.N6 U10.N7 U10.N11 U10.N13 U10.N14 U10.N15 U10.P2 U10.P4 U10.P5 U10.P6 U10.P7 U10.P8 U10.P9 U10.P10 U10.P11 U10.P12 U10.P13 U10.P14 U10.P15 U10.R2 U10.R3 U10.R6 U10.R7 U10.R8 U10.R9 U10.R10 U10.R11 U10.R12 U10.R13 U14.4 U18.7 U22.B1 U22.B5 U26.A1 U26.A2 U26.A7 U26.A8 U26.A9 U26.A10 U26.A11 U26.A12 U26.A13 U26.A14 U26.B1 U26.B7 U26.B8 U26.B9 U26.B10 U26.B11 U26.B12 U26.B13 U26.B14 U26.C1 U26.C3 U26.C5 U26.C7 U26.C8 U26.C9 U26.C10 U26.C11 U26.C12 U26.C13 U26.C14 U26.D1 U26.D2 U26.D3 U26.D4 U26.D12 U26.D13 U26.D14 U26.E1 U26.E2 U26.E3 U26.E5 U26.E8 U26.E9 U26.E10 U26.E12 U26.E13 U26.E14 U26.F1 U26.F2 U26.F3 U26.F10 U26.F12 U26.F13 U26.F14 U26.G1 U26.G2 U26.G3 U26.G10 U26.G12 U26.G13 U26.G14 U26.H1 U26.H2 U26.H3 U26.H12 U26.H13 U26.H14 U26.J1 U26.J2 U26.J3 U26.J12 U26.J13 U26.J14 U26.K1 U26.K2 U26.K3 U26.K6 U26.K7 U26.K10 U26.K12 U26.K13 U26.K14 U26.L1 U26.L2 U26.L3 U26.L12 U26.L13 U26.L14 U26.M1 U26.M2 U26.M3 U26.M7 U26.M8 U26.M9 U26.M10 U26.M11 U26.M12 U26.M13 U26.M14 U26.N1 U26.N3 U26.N6 U26.N7 U26.N8 U26.N9 U26.N10 U26.N11 U26.N12 U26.N13 U26.N14 U26.P1 U26.P2 U26.P7 U26.P8 U26.P9 U26.P10 U26.P11 U26.P12 U26.P13 U26.P14 U27.A1 U27.A2 U27.A7 U27.A8 U27.A9 U27.A10 U27.A11 U27.A12 U27.A13 U27.A14 U27.B1 U27.B7 U27.B8 U27.B9 U27.B10 U27.B11 U27.B12 U27.B13 U27.B14 U27.C1 U27.C3 U27.C5 U27.C7 U27.C8 U27.C9 U27.C10 U27.C11 U27.C12 U27.C13 U27.C14 U27.D1 U27.D2 U27.D3 U27.D4 U27.D12 U27.D13 U27.D14 U27.E1 U27.E2 U27.E3 U27.E5 U27.E8 U27.E9 U27.E10 U27.E12 U27.E13 U27.E14 U27.F1 U27.F2 U27.F3 U27.F10 U27.F12 U27.F13 U27.F14 U27.G1 U27.G2 U27.G3 U27.G10 U27.G12 U27.G13 U27.G14 U27.H1 U27.H2 U27.H3 U27.H12 U27.H13 U27.H14 U27.J1 U27.J2 U27.J3 U27.J12 U27.J13 U27.J14 U27.K1 U27.K2 U27.K3 U27.K6 U27.K7 U27.K10 U27.K12 U27.K13 U27.K14 U27.L1 U27.L2 U27.L3 U27.L12 U27.L13 U27.L14 U27.M1 U27.M2 U27.M3 U27.M7 U27.M8 U27.M9 U27.M10 U27.M11 U27.M12 U27.M13 U27.M14 U27.N1 U27.N3 U27.N6 U27.N7 U27.N8 U27.N9 U27.N10 U27.N11 U27.N12 U27.N13 U27.N14 U27.P1 U27.P2 U27.P7 U27.P8 U27.P9 U27.P10 U27.P11 U27.P12 U27.P13 U27.P14 U30.4 U31.2 U35.4
copper on no net:
  other v1: 13.675,107.125 14.325,107.125

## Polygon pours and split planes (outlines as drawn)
GND on Bottom Layer "C" (solid, remove dead copper, pour order 163): 5.2,111.977 90.15,111.977 92.975,109.152 92.975,2.452 89.725,-0.798 -0.45,-0.798 -2,0.752 -2,109.952 0.025,111.977
VDD_LCD on Bottom Layer "VDD_LCD" (solid, pour order 70): 47.3,67.171 46.425,66.296 46.1,65.971 45.45,65.971 45,66.421 45,72.346 45.2,72.546 45.2,72.746 45.475,73.021 46.425,73.021 47.3,72.146
5V_LCD on Bottom Layer "5V_LCD" (solid, pour order 42): 51.225,69.246 52.1,70.121 53.4,70.121 53.525,69.996 53.525,63.671 53.325,63.471 53.325,63.346 52.975,62.996 51.975,62.996 51.225,63.746
3V3_LCD on Bottom Layer "3V3_LCD" (solid, pour order 36): 47.525,69.246 48.4,70.121 49.7,70.121 49.825,69.996 49.825,64.409 49.525,64.109 49.525,63.996 49.2,63.671 48.125,63.671 47.525,64.271
1V8_LCD on Bottom Layer "1V8_LCD" (solid, pour order 32): 42.125,77.371 43,76.496 43.325,76.171 43.325,75.521 42.875,75.071 36.95,75.071 36.75,75.271 36.55,75.271 36.275,75.546 36.275,76.496 37.15,77.371
VDD_MCU on Bottom Layer "VDD_MCU" (solid, pour order 160): 64,52.808 62.408,52.808 61.875,52.275 61.875,51.325 62.045,51.155 63.805,51.155 64.8,52.15 64.8,52.559 64.559,52.8 64.35,52.8
NetC115_2 on Bottom Layer "NetC21_2" (solid, pour order 152): 75.45,100.325 76.325,101.2 77.175,101.2 77.35,101.025 77.35,100.025 77.6,99.775 78.925,99.775 79.575,99.125 79.575,98.033 79.492,97.95 78.72,97.95 78.145,98.525 77.279,98.525 77.029,98.775 75.725,98.775 75.45,99.05
GND on Bottom Layer "GND" (solid, pour order 149): 81.55,39.375 81.55,38.65 81.775,38.425 82.725,38.425 83,38.15 83,37.639 82.686,37.325 82.325,37.325 81.975,36.975 81.975,35.821 81.454,35.3 79.35,35.3 79.225,35.425 79.25,39.8 79.25,40.946 79.554,41.25 84.475,41.25 84.975,40.75 86.325,40.75 86.725,41.15 87.325,41.15 87.5,41.325 87.5,41.993 87.607,42.1 88.375,42.1 88.775,41.7 88.775,40.45 88.55,40.225 86.657,40.225 86.432,40.45 85.05,40.45 84.8,40.2 84.55,40.45 82.395,40.45 81.875,39.93 81.875,39.7
3V3_SMPS on Bottom Layer "3V3_SMPS" (solid, pour order 148): 79.575,41.375 81.795,41.375 82.175,41.755 82.175,47.075 82.7,47.6 82.7,50.42 82.32,50.8 80.353,50.8 79.025,49.472 79.025,46.925 79.025,41.722 79.375,41.372
NetL6_1 on Bottom Layer "NetL2_1" (solid, pour order 147): 84.586,46.972 84.836,46.722 84.836,41.548 84.635,41.347 83.323,41.347 83.264,41.407 83.264,42.105 82.511,42.858 82.511,46.497 82.986,46.972
GND on Bottom Layer "GND" (solid, pour order 145): 68.95,40.575 69.475,40.575 69.725,40.825 69.725,41.559 70.172,42.007 70.874,42.007 71.527,41.354 72.172,41.354 73.325,40.201 73.325,38.35 73,38.025 68.825,38.05 67.625,38.05 67.35,38.325 67.35,40.9 67.001,41.249 67.001,42.214 67.225,42.438 67.225,43.625 67.73,44.13 67.73,45.895 67.359,46.266 66.647,46.266 66.472,46.441 66.472,47.122 66.848,47.498 68.087,47.498 68.4,47.185 68.4,45.548 68.025,45.173 68.025,44.275 68.972,43.328 68.972,42.605 68.793,42.425 68.325,42.425 68.15,42.25 68.15,41.375
VDDMCU_SMPS on Bottom Layer "VDDMCU_SMPS" (solid, pour order 144): 66.778,40.9 67.004,40.675 67.004,38.261 66.692,37.95 62.895,37.95 62.425,37.48 62.425,35.35 62.125,35.05 56.175,35.05 55.975,35.25 55.975,37.475 56.375,37.875 57.875,37.875 60.9,40.9
NetL7_1 on Bottom Layer "NetL3_1" (solid, pour order 143): 61.5,43.65 61.75,43.9 66.924,43.9 67.125,43.699 67.125,42.387 67.066,42.328 66.367,42.328 65.614,41.575 61.975,41.575 61.5,42.05
IOREF on Bottom Layer "IOREF" (solid, pour order 120): 63.28,56.65 62.144,55.514 62.144,53.206 62.375,52.975 64.5,52.975 65.725,51.75 67.392,51.75 70.039,54.396 70.039,57.087 69.372,57.753 68.6,57.753 67.497,56.65
5V_USB_CHGR on Bottom Layer "NO_TH" (solid, pour order 92): 63.6,5.023 64.3,4.323 64.3,3.7 63.9,3.3 63.9,2.2 68.6,2.2 69.1,2.7 69.5,2.7 71.05,4.25 71.05,5.025 75.918,9.893 75.918,18.857 75.1,19.675 75.1,23.639 75.336,23.875 75.725,23.875 75.918,24.068 75.918,24.457 75.725,24.65 73.325,24.65 73.225,24.8 73.225,27.025 72.772,27.478 72.772,28.753 71.375,30.15 71.375,33.2 70.95,33.625 68.85,33.625 67.9,32.675 67.9,29.1 69.127,27.873 69.127,25.873 70.7,24.325 70.7,18.061 71.85,16.911 71.85,11.525 68.925,8.6 63.15,8.6 62.65,8.1 62.65,5.547 63.175,5.023
5V on Bottom Layer "5V" (solid, pour order 76): 75.125,37.65 74.775,38 74.775,39.679 74.65,39.804 73.624,39.804 73.5,39.68 73.5,38 73.15,37.65 69.525,37.65 68.6,36.75 68.6,36.475 68.4,36.275 66.95,36.275 66.775,36.1 66.775,35.15 67.175,34.75 67.175,33.75 67.475,33.45 68.325,33.45 68.7,33.825 70.975,33.825 71.4,33.4 78.375,33.4 79.075,34.1 79.075,36.2 77.625,37.65
NetCN9_9 on Bottom Layer "NetCN11_9" (solid, pour order 161): 70.675,65.075 71.3,64.45 71.3,63.34 70.235,62.275 68,62.275 67.525,62.75 67.525,64.35 68.25,65.075
VDD on Bottom Layer "VDD_L01_P-001" (solid, pour order 30): 63.8,52.3 62.3,52.3 62.1,52.1 62.1,51.3 62.2,51.2 63.8,51.2 64.6,52 64.6,52.6 64.1,52.6
1V8_AUDIO on Bottom Layer "1V8_Audio" (solid, pour order 132): 27.695,91.955 27.2,91.955 26.825,92.33 26.825,93.659 27.666,94.5 33.3,94.525 36.875,94.525 37.925,93.475 37.925,91.65 34.8,88.525 34.8,86.275 34.565,86.04 33.61,86.04
2V8 on Bottom Layer "2V8" (solid, pour order 159): 84.761,96.5 84.85,96.411 84.85,95.193 84.007,94.35 83.25,94.35 82.775,94.825 82.775,96.365 82.91,96.5
NetR60_2 on Bottom Layer "NetR191_1" (solid, pour order 155): 83.35,97.7 83.625,97.975 86.075,97.975 86.575,97.475 86.575,95.649 86.151,95.225 85.177,95.225 85.052,95.35 85.052,96.573 84.825,96.8 83.625,96.8 83.35,97.075
NetC116_2 on Bottom Layer "NetC150_2" (solid, pour order 154): 80.025,97.95 79.775,97.7 79.775,96.5 80.125,96.15 81.025,96.15 81.764,96.889 82.714,96.889 82.875,97.05 82.875,97.75 82.675,97.95
NetR59_1 on Bottom Layer "NetR150_2" (solid, pour order 153): 72.096,100.1 74.683,100.1 74.975,99.808 74.975,99 74.775,98.8 73.4,98.8 73.05,99.15 72,99.15 71.75,99.4 71.75,99.925 71.925,100.1
1V8 on Bottom Layer "1V8" (solid, pour order 142): 68.35,98.45 68.875,98.975 72.966,98.975 73.225,98.716 73.225,97.775 73.075,97.625 68.65,97.625 68.35,97.925
5V on Bottom Layer "5V" (solid, pour order 151): 71.775,64 72.325,64 72.325,62.625 72.025,62.325 71.25,62.325 71.05,62.525 71.05,62.925 71.275,63.15 71.575,63.15 71.725,63.3 71.725,63.905 71.77,63.95
VIN on Bottom Layer "VIN" (solid, pour order 150): 82.675,39.743 82.443,39.743 82.35,39.65 82.35,39.325 83.129,38.546 83.129,37.657 82.4,36.928 82.4,35.5 83.025,34.875 83.025,33.879 83.229,33.675 84.175,33.675 84.325,33.825 84.325,34.525 84.325,38.225 84.15,38.4 84.15,39.197 84.097,39.25 83.4,39.25 83.15,39.5
5VIN on Bottom Layer "5VIN" (solid, pour order 146): 73.825,43.275 74.025,43.075 74.025,42 74.8,41.225 74.8,40.366 74.65,40.216 73.584,40.216 72.275,41.525 71.475,41.525 70.9,42.1 69.944,42.1 69.269,41.425 68.75,41.425 68.725,41.45 68.725,42.167 68.772,42.214 68.988,42.214 69.222,42.449 69.222,43.222 69.275,43.275
GND on Top Layer "GND" (solid, remove dead copper, pour order 157): 5.199,111.925 90.149,111.925 92.974,109.1 92.974,2.4 89.724,-0.85 -0.451,-0.85 -2.001,0.7 -2.001,109.9 0.024,111.925
BLGND on Top Layer "BLGND" (solid, pour order 136): 50.979,83.096 51.175,82.9 51.175,82.444 50.831,82.1 50.289,82.1 50.125,82.264 50.125,82.93 50.291,83.096
NetC119_1 on Top Layer "NetC43_1" (solid, pour order 135): 51.75,83.1 51.625,82.975 51.625,82.346 51.942,82.029 52.442,82.029 52.643,82.231 52.643,82.95 52.497,83.096
2V8 on Top Layer "2V8" (solid, pour order 130): 6.85,81.4 6.85,82.125 7.275,82.55 8.475,82.55 8.475,81.35 8.2,81.075 7.175,81.075
VDD_SMPS on Top Layer "NO_TH" (solid, pour order 86): 46.1,32.4 46.7,33 47.6,33 48.4,32.2 48.9,32.2 49.3,32.2 49.3,33.2 48.25,34.25 46.3,34.25 44.27,34.25 43.95,33.93 43.95,32.076 43.9,32.026 43.9,31.567 44.123,31.344 44.344,31.344 45.4,32.4
5V_VIN on Top Layer "5V_VIN" (solid, pour order 84): 77.05,47.775 77.65,47.175 77.65,37.702 79.525,35.827 79.525,30.875 77.775,29.125 74.65,29.125 73.539,30.236 73.539,36.064 75,37.525 75,46.4 76.375,47.775
3V3 on Top Layer "3V3" (solid, pour order 82): 12.453,44.022 11.6,44.875 10.568,44.875 10.025,44.332 10.025,30.568 10.951,29.624 11.225,29.35 12.125,29.35 12.45,29.675 12.45,41.075 12.453,41.078
3V3 on Top Layer "3V3" (solid, pour order 80): 81.375,62.875 85.4,58.85 85.4,48.261 84.739,47.6 82.971,47.6 82.35,48.221 82.35,57.775 80.6,59.525 69.7,59.539 65.686,59.539 65.675,59.55 64.45,58.325 58.175,58.325 57.75,57.9 53.819,57.9 50.972,55.053 48.528,55.053 34.628,55.053 30.965,51.39 29.71,51.39 29.325,51.775 29.325,52.825 33.6,57.1 49.881,57.1 53.531,60.75 57.527,60.75 62.425,60.75 64.55,62.875
5V_USB_CHGR on Top Layer "NO_TH" (solid, pour order 78): 64.5,3.9 63.9,3.3 63.9,2.9 64.1,2.7 65.1,2.7 65.2,2.8 65.2,3.3 65.023,3.475 65.023,6.127 64.75,6.4 64.75,6.775 64.6,6.925 63,6.925 62.775,6.7 62.775,5.575 63.35,5 64,5 64.5,4.5
VDD_HEXASPI on Top Layer "NO_TH" (solid, pour order 56): 38.8,9.05 39.3,9.05 42.2,11.95 46.425,11.95 46.725,12.25 46.725,12.8 46.375,13.15 43.075,13.15 40.425,15.8 39.825,15.8 39.625,15.6 39.625,12 38.6,10.975 38.6,9.275
AVDD_TOF_SENSOR on Top Layer "AVDD_TOF_SENSOR" (solid, pour order 139): 5.625,81.026 5.625,81.025 5.875,80.775 5.875,79.75 5.975,79.65 6.525,79.65 6.525,80.125 6.6,80.2 6.6,81.075 6.525,81.15 6.525,81.5 6.305,81.72 6.149,81.72 5.894,81.975 5.9,83.225 5.9,83.65 5.35,84.2 4.625,84.2 4.625,83.675 5.2,83.1 5.2,82.05 4.875,81.725 4.925,81.675 4.925,81.301 5.034,81.192 5.525,81.192 5.525,81.072 5.571,81.026
NetCN9_1 on Top Layer "NetCN11_1" (solid, pour order 156): 75.634,48.934 75,49.568 75,51.5 74.5,52.039 71.9,52.039 70.561,50.7 68,50.7 67.6,51.1 67.575,52.4 67.575,54.466 68.134,55.025 76.025,55.025 77.75,53.3 77.75,48.978 76.98,48.207 76.375,48.193
VDD on Signal Layer 2 "VDD" (solid, remove dead copper, pour order 129): 5.2,111.875 90.15,111.875 92.975,109.05 92.975,2.35 89.725,-0.9 -0.45,-0.9 -2,0.65 -2,109.85 0.025,111.875
3V3 on Signal Layer 2 "3V3" (solid, pour order 127): 11.652,46.982 15.701,46.982 16.382,46.294 19.95,42.725 23.975,42.725 24.75,43.5 24.75,50.8 26.45,52.5 31.175,52.5 31.625,52.05 31.625,51.175 31.1,50.65 27.585,50.65 26.5,49.565 26.5,42.425 24.85,40.775 18.725,40.775 15.653,43.847 11.353,43.847 10.925,44.275 10.925,46.255
5V on Signal Layer 2 "5V" (solid, pour order 128): 78.375,33.4 68.625,33.4 68.125,33.9 68.125,36.525 69.25,37.65 77.6,37.65 79.044,36.206 79.044,34.069
5V_UCPD on Signal Layer 2 "NO_TH" (solid, remove dead copper, pour order 125): 73.4,33.75 73.425,33.725 76.275,33.725 76.625,33.375 76.625,31.425 77.075,30.985 79,30.985 79,1.2 78.8,1 18.575,1 18.575,6.421 15.145,9.85 11.7,9.85 11.3,10.25 11.3,11.095 12.6,12.395 12.6,14.575 14.963,16.938 17.413,16.938 17.875,16.475 17.875,15.8 17.575,15.5 15.975,15.5 15.55,15.075 15.55,14.597 18.699,11.448 19.727,11.448 24.45,6.725 27.328,6.725 28.252,7.649 29.175,8.575 67.35,8.575 67.649,8.874 67.649,11.124 73.625,17.1 73.625,25.325 71,27.95 71,33.4 71.35,33.75
VBUSc on Signal Layer 2 "VBUSc" (solid, pour order 122): 21.519,11.556 23.25,9.825 23.25,9.25 23.458,9.042 26.192,9.042 27.05,9.9 27.05,11.875 24.075,14.85 24.075,16.45 23.675,16.85 21.25,16.85 21.248,16.848 19.975,16.848 19.05,16.85 17.6,15.4 15.65,15.4 15.225,14.975 15.225,13.875 15.75,13.35 16.95,13.35 18.744,11.556
3V3_STLK on Signal Layer 2 "3V3_STLK" (solid, pour order 121): 50.7,8.65 50.425,8.925 50.425,17.55 50.625,17.75 53.625,17.75 56.65,20.775 61.8,20.775 66.275,16.3 66.275,12.275 67.5,11.05 67.5,8.9 67.25,8.65
VDD_MCU on Signal Layer 2 "VDD_MCU" (solid, remove dead copper, pour order 119): 56.4,37.5 56.4,32.575 52.125,28.3 41.125,28.3 37.65,28.3 33,28.3 32.55,28.75 32.55,39.05 32.925,39.425 54.175,39.425
V11 on Signal Layer 2 "V11" (solid, pour order 118): 44.575,31.2 44.425,31.05 43.95,31.05 43.75,31.25 36.975,31.25 36.525,31.7 36.525,32.25 36.65,32.375 37.075,32.375 37.4,32.7 37.4,35.125 38.775,36.5 38.825,36.825 38.825,37.825 38.675,37.975 38.125,37.975 37.5,37.35 35.2,37.35 34.95,37.1 34.95,36.5 35.2,36.25 35.875,36.25 36.475,35.65 36.475,34.7 34.925,33.15 34.925,30.225 35.4,29.75 44.8,29.75 45.075,30.025 45.075,31 44.875,31.2
VCCQ_eMMC on Signal Layer 2 "VCCQ_eMMC" (solid, pour order 123): 16.625,28.45 15.675,29.4 15.675,36.9 15.55,36.975 13,39.525 13,40.05 13.225,40.275 13.775,40.275 13.95,40.1 23.5,40.1 24,39.6 24,38.925 23.575,38.5 20.975,38.5 19.85,37.375 19.85,21.875 19.65,21.675 16.875,21.675 16.625,21.925 16.625,22.9
VDD_OCTOSPI on Signal Layer 2 "VDD_OCTOSPI" (solid, remove dead copper, pour order 124): 54.775,47.525 55.525,46.775 56.35,46.775 56.525,46.95 56.525,49.791 53.491,52.825 50.125,52.825 49.85,52.55 49.85,48.375 50.7,47.525
VDD_HEXASPI on Signal Layer 2 "NO_TH" (solid, pour order 126): 38.8,9.05 39.3,9.05 42.2,11.95 46.425,11.95 46.825,12.35 46.825,12.7 46.375,13.15 43.075,13.15 40.425,15.8 39.825,15.8 39.625,15.6 39.625,12 38.6,10.975 38.6,9.275
GND on Signal Layer 1 "GND" (solid, pour order 133): 5.2,111.925 90.15,111.925 92.975,109.1 92.975,2.4 89.725,-0.85 -0.45,-0.85 -2,0.7 -2,109.9 0.025,111.925
AGND on Signal Layer 1 "AGND" (solid, pour order 114): 39.85,35.65 40.3,35.65 40.475,35.825 40.475,36.25 40.675,36.45 43.425,36.45 44.15,35.725 44.975,35.725 45.225,35.975 45.225,38.625 45.075,38.775 43.15,38.775 42.7,38.325 39.975,38.325 39.675,38.025 39.675,35.825
GND on Signal Layer 1 "GND" (solid, pour order 115): 38.806,40.25 39.75,41.194 39.75,43.79 40.785,44.825 43.584,44.825 43.975,44.434 43.975,41.925 44.975,40.925 44.975,39.725 43.425,38.175 43.4,37.225 43.4,31.925 40.75,29.275 35.55,29.275 32.875,31.95 32.875,37.1 36.025,40.25
GND on Signal Layer 4 "GND" (solid, pour order 134): 5.2,111.925 90.15,111.925 92.975,109.1 92.975,2.4 89.725,-0.85 -0.45,-0.85 -2,0.7 -2,109.9 0.025,111.925
A_GND on Signal Layer 4 "A_GND" (solid, pour order 113): 62.4,96.15 61.55,95.3 51.763,95.3 48.688,92.225 45.85,92.225 44.8,91.175 42.25,91.175 41.05,89.975 41.05,88.775 37.754,85.479 34.958,85.479 34.475,85.962 34.475,91.9 35.75,93.175 35.75,95.908 32.933,98.725 31.7,98.725 31.3,99.125 31.3,100.225 32.475,101.4 49.551,101.401 50.948,102.798 50.948,105.304 51.769,106.125 54.275,106.125 57.15,109 62.075,109 62.4,108.675
GND on Signal Layer 4 "GND" (solid, pour order 111): 27.025,46.05 27.025,24.075 27.875,23.225 50.675,23.225 54.375,26.925 54.375,44.15 50.6,47.925 28.9,47.925
GND on Signal Layer 3 "GND" (solid, remove dead copper, pour order 158): 5.2,111.886 90.15,111.886 92.975,109.061 92.975,2.361 89.725,-0.889 -0.45,-0.889 -2,0.661 -2,109.861 0.025,111.886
